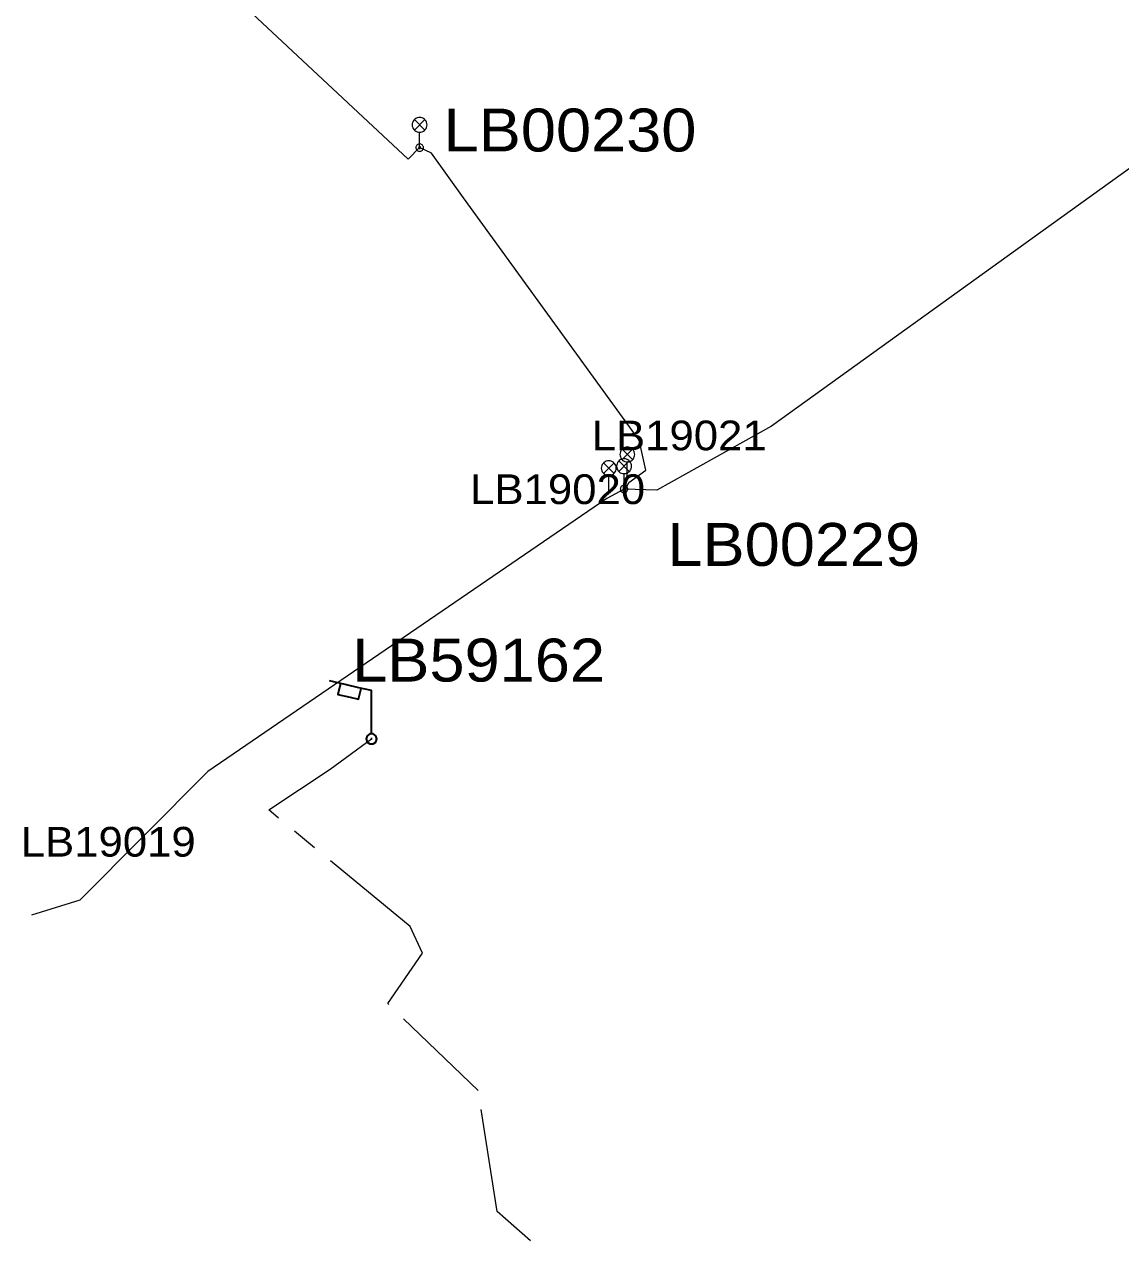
# Model space of a CAD drawing. Extents: x -688049 to -687261, y -973611 to -973038.
# Drawn here: x -687873.1 to -687817.8, y -973598.4 to -973537 of the extents above; entities that cross this region are included whole.
import ezdxf

# ---------------------------------------------------------------- set-up
doc = ezdxf.new("R2010")
doc.units = 0
doc.header["$LTSCALE"] = 0.87
doc.linetypes.add('LONG_DASH_SHORT_DASH', pattern=[9.9, 6, -1.2, 1.5, -1.2])
doc.layers.add('1', color=7, linetype='Continuous', lineweight=13)

msp = doc.modelspace()

# ---------------------------------------------------------------- linework, layer by layer
at = {"layer": '1'}
for p, q in [((-687853.445, -973541.765), (-687852.915, -973542.295)), ((-687853.445, -973542.295), (-687852.915, -973541.765)), ((-687853.18, -973543.18), (-687853.18, -973542.405)), ((-687842.96, -973558.407), (-687842.43, -973558.937)), ((-687842.96, -973558.937), (-687842.43, -973558.407)), ((-687843.897, -973559.102), (-687843.367, -973559.632)), ((-687843.897, -973559.632), (-687843.367, -973559.102)), ((-687843.125, -973559.005), (-687842.595, -973559.535)), ((-687843.125, -973559.535), (-687842.595, -973559.005)), ((-687842.695, -973559.822), (-687842.695, -973559.047)), ((-687843.632, -973560.517), (-687843.632, -973559.742)), ((-687842.86, -973560.42), (-687842.86, -973559.645))]:
    msp.add_line(p, q, dxfattribs=at)
at = {"layer": '1', "lineweight": 35}
msp.add_line((-687855.583, -973573.04), (-687855.637, -973573.04), dxfattribs=at)
at = {"layer": '1'}
for points in [[(-687868.985, -973528.975), (-687869.24, -973529.284), (-687853.757, -973543.759), (-687853.18, -973543.18)], [(-687809.727, -973538.075), (-687809.727, -973538.771), (-687821.294, -973547.087), (-687835.424, -973557.246), (-687841.213, -973560.485), (-687842.86, -973560.42)], [(-687842.86, -973560.61), (-687842.623, -973560.089), (-687841.765, -973559.475), (-687842.104, -973557.958), (-687850.966, -973545.716), (-687852.578, -973543.455), (-687853.18, -973543.18)], [(-687842.86, -973560.42), (-687843.729, -973560.901), (-687863.881, -973574.682), (-687870.344, -973581.188), (-687872.782, -973581.935)]]:
    msp.add_lwpolyline(points, dxfattribs=at)
for points in [[(-687852.805, -973542.03), (-687852.811, -973541.965), (-687852.828, -973541.902), (-687852.855, -973541.842), (-687852.893, -973541.789), (-687852.939, -973541.743), (-687852.992, -973541.705), (-687853.052, -973541.678), (-687853.115, -973541.661), (-687853.18, -973541.655), (-687853.245, -973541.661), (-687853.308, -973541.678), (-687853.368, -973541.705), (-687853.421, -973541.743), (-687853.467, -973541.789), (-687853.505, -973541.842), (-687853.532, -973541.902), (-687853.549, -973541.965), (-687853.555, -973542.03), (-687853.549, -973542.095), (-687853.532, -973542.158), (-687853.505, -973542.218), (-687853.467, -973542.271), (-687853.421, -973542.317), (-687853.368, -973542.355), (-687853.308, -973542.382), (-687853.245, -973542.399), (-687853.18, -973542.405), (-687853.115, -973542.399), (-687853.052, -973542.382), (-687852.992, -973542.355), (-687852.939, -973542.317), (-687852.893, -973542.271), (-687852.855, -973542.218), (-687852.828, -973542.158), (-687852.811, -973542.095)], [(-687852.99, -973543.18), (-687852.993, -973543.147), (-687853.001, -973543.115), (-687853.015, -973543.085), (-687853.034, -973543.058), (-687853.058, -973543.034), (-687853.085, -973543.015), (-687853.115, -973543.001), (-687853.147, -973542.993), (-687853.18, -973542.99), (-687853.213, -973542.993), (-687853.245, -973543.001), (-687853.275, -973543.015), (-687853.302, -973543.034), (-687853.326, -973543.058), (-687853.345, -973543.085), (-687853.359, -973543.115), (-687853.367, -973543.147), (-687853.37, -973543.18), (-687853.367, -973543.213), (-687853.359, -973543.245), (-687853.345, -973543.275), (-687853.326, -973543.302), (-687853.302, -973543.326), (-687853.275, -973543.345), (-687853.245, -973543.359), (-687853.213, -973543.367), (-687853.18, -973543.37), (-687853.147, -973543.367), (-687853.115, -973543.359), (-687853.085, -973543.345), (-687853.058, -973543.326), (-687853.034, -973543.302), (-687853.015, -973543.275), (-687853.001, -973543.245), (-687852.993, -973543.213)], [(-687853.13, -973543.18), (-687853.131, -973543.171), (-687853.133, -973543.163), (-687853.137, -973543.155), (-687853.142, -973543.148), (-687853.148, -973543.142), (-687853.155, -973543.137), (-687853.163, -973543.133), (-687853.171, -973543.131), (-687853.18, -973543.13), (-687853.189, -973543.131), (-687853.197, -973543.133), (-687853.205, -973543.137), (-687853.212, -973543.142), (-687853.218, -973543.148), (-687853.223, -973543.155), (-687853.227, -973543.163), (-687853.229, -973543.171), (-687853.23, -973543.18), (-687853.229, -973543.189), (-687853.227, -973543.197), (-687853.223, -973543.205), (-687853.218, -973543.212), (-687853.212, -973543.218), (-687853.205, -973543.223), (-687853.197, -973543.227), (-687853.189, -973543.229), (-687853.18, -973543.23), (-687853.171, -973543.229), (-687853.163, -973543.227), (-687853.155, -973543.223), (-687853.148, -973543.218), (-687853.142, -973543.212), (-687853.137, -973543.205), (-687853.133, -973543.197), (-687853.131, -973543.189)], [(-687842.32, -973558.672), (-687842.326, -973558.607), (-687842.343, -973558.544), (-687842.37, -973558.484), (-687842.408, -973558.431), (-687842.454, -973558.385), (-687842.508, -973558.347), (-687842.567, -973558.32), (-687842.63, -973558.303), (-687842.695, -973558.297), (-687842.76, -973558.303), (-687842.823, -973558.32), (-687842.883, -973558.347), (-687842.936, -973558.385), (-687842.982, -973558.431), (-687843.02, -973558.484), (-687843.047, -973558.544), (-687843.064, -973558.607), (-687843.07, -973558.672), (-687843.064, -973558.737), (-687843.047, -973558.8), (-687843.02, -973558.86), (-687842.982, -973558.913), (-687842.936, -973558.959), (-687842.883, -973558.997), (-687842.823, -973559.024), (-687842.76, -973559.041), (-687842.695, -973559.047), (-687842.63, -973559.041), (-687842.567, -973559.024), (-687842.508, -973558.997), (-687842.454, -973558.959), (-687842.408, -973558.913), (-687842.37, -973558.86), (-687842.343, -973558.8), (-687842.326, -973558.737)], [(-687842.485, -973559.27), (-687842.491, -973559.205), (-687842.508, -973559.142), (-687842.535, -973559.082), (-687842.573, -973559.029), (-687842.619, -973558.983), (-687842.672, -973558.945), (-687842.732, -973558.918), (-687842.795, -973558.901), (-687842.86, -973558.895), (-687842.925, -973558.901), (-687842.988, -973558.918), (-687843.048, -973558.945), (-687843.101, -973558.983), (-687843.147, -973559.029), (-687843.185, -973559.082), (-687843.212, -973559.142), (-687843.229, -973559.205), (-687843.235, -973559.27), (-687843.229, -973559.335), (-687843.212, -973559.398), (-687843.185, -973559.458), (-687843.147, -973559.511), (-687843.101, -973559.557), (-687843.048, -973559.595), (-687842.988, -973559.622), (-687842.925, -973559.639), (-687842.86, -973559.645), (-687842.795, -973559.639), (-687842.732, -973559.622), (-687842.672, -973559.595), (-687842.619, -973559.557), (-687842.573, -973559.511), (-687842.535, -973559.458), (-687842.508, -973559.398), (-687842.491, -973559.335)], [(-687843.257, -973559.367), (-687843.263, -973559.302), (-687843.28, -973559.239), (-687843.307, -973559.18), (-687843.345, -973559.126), (-687843.391, -973559.08), (-687843.444, -973559.042), (-687843.504, -973559.015), (-687843.567, -973558.998), (-687843.632, -973558.992), (-687843.697, -973558.998), (-687843.76, -973559.015), (-687843.82, -973559.042), (-687843.873, -973559.08), (-687843.919, -973559.126), (-687843.957, -973559.18), (-687843.984, -973559.239), (-687844.001, -973559.302), (-687844.007, -973559.367), (-687844.001, -973559.432), (-687843.984, -973559.495), (-687843.957, -973559.554), (-687843.919, -973559.608), (-687843.873, -973559.654), (-687843.82, -973559.692), (-687843.76, -973559.719), (-687843.697, -973559.736), (-687843.632, -973559.742), (-687843.567, -973559.736), (-687843.504, -973559.719), (-687843.444, -973559.692), (-687843.391, -973559.654), (-687843.345, -973559.608), (-687843.307, -973559.554), (-687843.28, -973559.495), (-687843.263, -973559.432)], [(-687842.67, -973560.42), (-687842.673, -973560.387), (-687842.681, -973560.355), (-687842.695, -973560.325), (-687842.714, -973560.298), (-687842.738, -973560.274), (-687842.765, -973560.255), (-687842.795, -973560.241), (-687842.827, -973560.233), (-687842.86, -973560.23), (-687842.893, -973560.233), (-687842.925, -973560.241), (-687842.955, -973560.255), (-687842.982, -973560.274), (-687843.006, -973560.298), (-687843.025, -973560.325), (-687843.039, -973560.355), (-687843.047, -973560.387), (-687843.05, -973560.42), (-687843.047, -973560.453), (-687843.039, -973560.485), (-687843.025, -973560.515), (-687843.006, -973560.542), (-687842.982, -973560.566), (-687842.955, -973560.585), (-687842.925, -973560.599), (-687842.893, -973560.607), (-687842.86, -973560.61), (-687842.827, -973560.607), (-687842.795, -973560.599), (-687842.765, -973560.585), (-687842.738, -973560.566), (-687842.714, -973560.542), (-687842.695, -973560.515), (-687842.681, -973560.485), (-687842.673, -973560.453)], [(-687842.81, -973560.42), (-687842.811, -973560.411), (-687842.813, -973560.403), (-687842.817, -973560.395), (-687842.822, -973560.388), (-687842.828, -973560.382), (-687842.835, -973560.377), (-687842.843, -973560.373), (-687842.851, -973560.371), (-687842.86, -973560.37), (-687842.869, -973560.371), (-687842.877, -973560.373), (-687842.885, -973560.377), (-687842.892, -973560.382), (-687842.898, -973560.388), (-687842.903, -973560.395), (-687842.907, -973560.403), (-687842.909, -973560.411), (-687842.91, -973560.42), (-687842.909, -973560.429), (-687842.907, -973560.437), (-687842.903, -973560.445), (-687842.898, -973560.452), (-687842.892, -973560.458), (-687842.885, -973560.463), (-687842.877, -973560.467), (-687842.869, -973560.469), (-687842.86, -973560.47), (-687842.851, -973560.469), (-687842.843, -973560.467), (-687842.835, -973560.463), (-687842.828, -973560.458), (-687842.822, -973560.452), (-687842.817, -973560.445), (-687842.813, -973560.437), (-687842.811, -973560.429)]]:
    msp.add_lwpolyline(points, close=True, dxfattribs=at)
at = {"layer": '1', "lineweight": 35}
for points in [[(-687855.61, -973572.785), (-687855.697, -973572.785), (-687855.832, -973572.883), (-687855.886, -973573.04), (-687855.832, -973573.197), (-687855.697, -973573.295), (-687855.529, -973573.295), (-687855.393, -973573.197), (-687855.339, -973573.04), (-687855.393, -973572.883), (-687855.529, -973572.785), (-687855.61, -973572.785), (-687855.61, -973572.097), (-687855.61, -973571.409), (-687855.61, -973570.721), (-687855.61, -973570.602), (-687856.244, -973570.455), (-687856.878, -973570.309), (-687857.512, -973570.163), (-687857.723, -973570.114)], [(-687857.181, -973570.249), (-687857.317, -973570.791), (-687856.683, -973570.938), (-687856.26, -973571.035), (-687856.125, -973570.493)]]:
    msp.add_lwpolyline(points, dxfattribs=at)
at = {"layer": '1', "linetype": 'LONG_DASH_SHORT_DASH'}
msp.add_lwpolyline([(-687847.59, -973598.38), (-687849.26, -973596.91), (-687850.22, -973590.79), (-687854.79, -973586.41), (-687853.03, -973583.86), (-687853.66, -973582.52), (-687860.8, -973576.63), (-687857.7, -973574.57), (-687855.61, -973573.04)], dxfattribs=at)
msp.add_lwpolyline([(-687847.59, -973598.38), (-687849.26, -973596.91), (-687850.22, -973590.79), (-687854.79, -973586.41), (-687853.03, -973583.86), (-687853.66, -973582.52), (-687860.8, -973576.63), (-687857.7, -973574.57), (-687855.61, -973573.04)], dxfattribs=at)
msp.add_lwpolyline([(-687847.59, -973598.38), (-687849.26, -973596.91), (-687850.22, -973590.79), (-687854.79, -973586.41), (-687853.03, -973583.86), (-687853.66, -973582.52), (-687860.8, -973576.63), (-687857.7, -973574.57), (-687855.61, -973573.04)], dxfattribs=at)
msp.add_lwpolyline([(-687847.59, -973598.38), (-687849.26, -973596.91), (-687850.22, -973590.79), (-687854.79, -973586.41), (-687853.03, -973583.86), (-687853.66, -973582.52), (-687860.8, -973576.63), (-687857.7, -973574.57), (-687855.61, -973573.04)], dxfattribs=at)
msp.add_lwpolyline([(-687847.59, -973598.38), (-687849.26, -973596.91), (-687850.22, -973590.79), (-687854.79, -973586.41), (-687853.03, -973583.86), (-687853.66, -973582.52), (-687860.8, -973576.63), (-687857.7, -973574.57), (-687855.61, -973573.04)], dxfattribs=at)
msp.add_lwpolyline([(-687847.59, -973598.38), (-687849.26, -973596.91), (-687850.22, -973590.79), (-687854.79, -973586.41), (-687853.03, -973583.86), (-687853.66, -973582.52), (-687860.8, -973576.63), (-687857.7, -973574.57), (-687855.61, -973573.04)], dxfattribs=at)
msp.add_lwpolyline([(-687847.59, -973598.38), (-687849.26, -973596.91), (-687850.22, -973590.79), (-687854.79, -973586.41), (-687853.03, -973583.86), (-687853.66, -973582.52), (-687860.8, -973576.63), (-687857.7, -973574.57), (-687855.61, -973573.04)], dxfattribs=at)
msp.add_lwpolyline([(-687847.59, -973598.38), (-687849.26, -973596.91), (-687850.22, -973590.79), (-687854.79, -973586.41), (-687853.03, -973583.86), (-687853.66, -973582.52), (-687860.8, -973576.63), (-687857.7, -973574.57), (-687855.61, -973573.04)], dxfattribs=at)

# ---------------------------------------------------------------- texts
at = {"layer": '1', "width": 1.1}
for s, height, p in [('LB00230', 2.167, (-687851.969, -973543.375)), ('LB19021', 1.5, (-687844.494, -973558.465)), ('LB19020', 1.5, (-687850.63, -973561.181)), ('LB00229', 2.167, (-687840.672, -973564.303)), ('LB59162', 2.168, (-687856.587, -973570.144)), ('LB19019', 1.5, (-687873.319, -973578.985))]:
    msp.add_text(s, height=height, dxfattribs=at).set_placement(p)

doc.saveas('drawing.dxf')
